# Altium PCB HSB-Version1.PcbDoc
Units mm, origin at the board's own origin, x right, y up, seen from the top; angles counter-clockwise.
Board outline 50.75 x 45.25 mm, 2 copper layers (Top Layer, Bottom Layer); 31 components, 31 nets, 155 pads, 0 vias.
Unrouted connection lines stored in the file: 86.
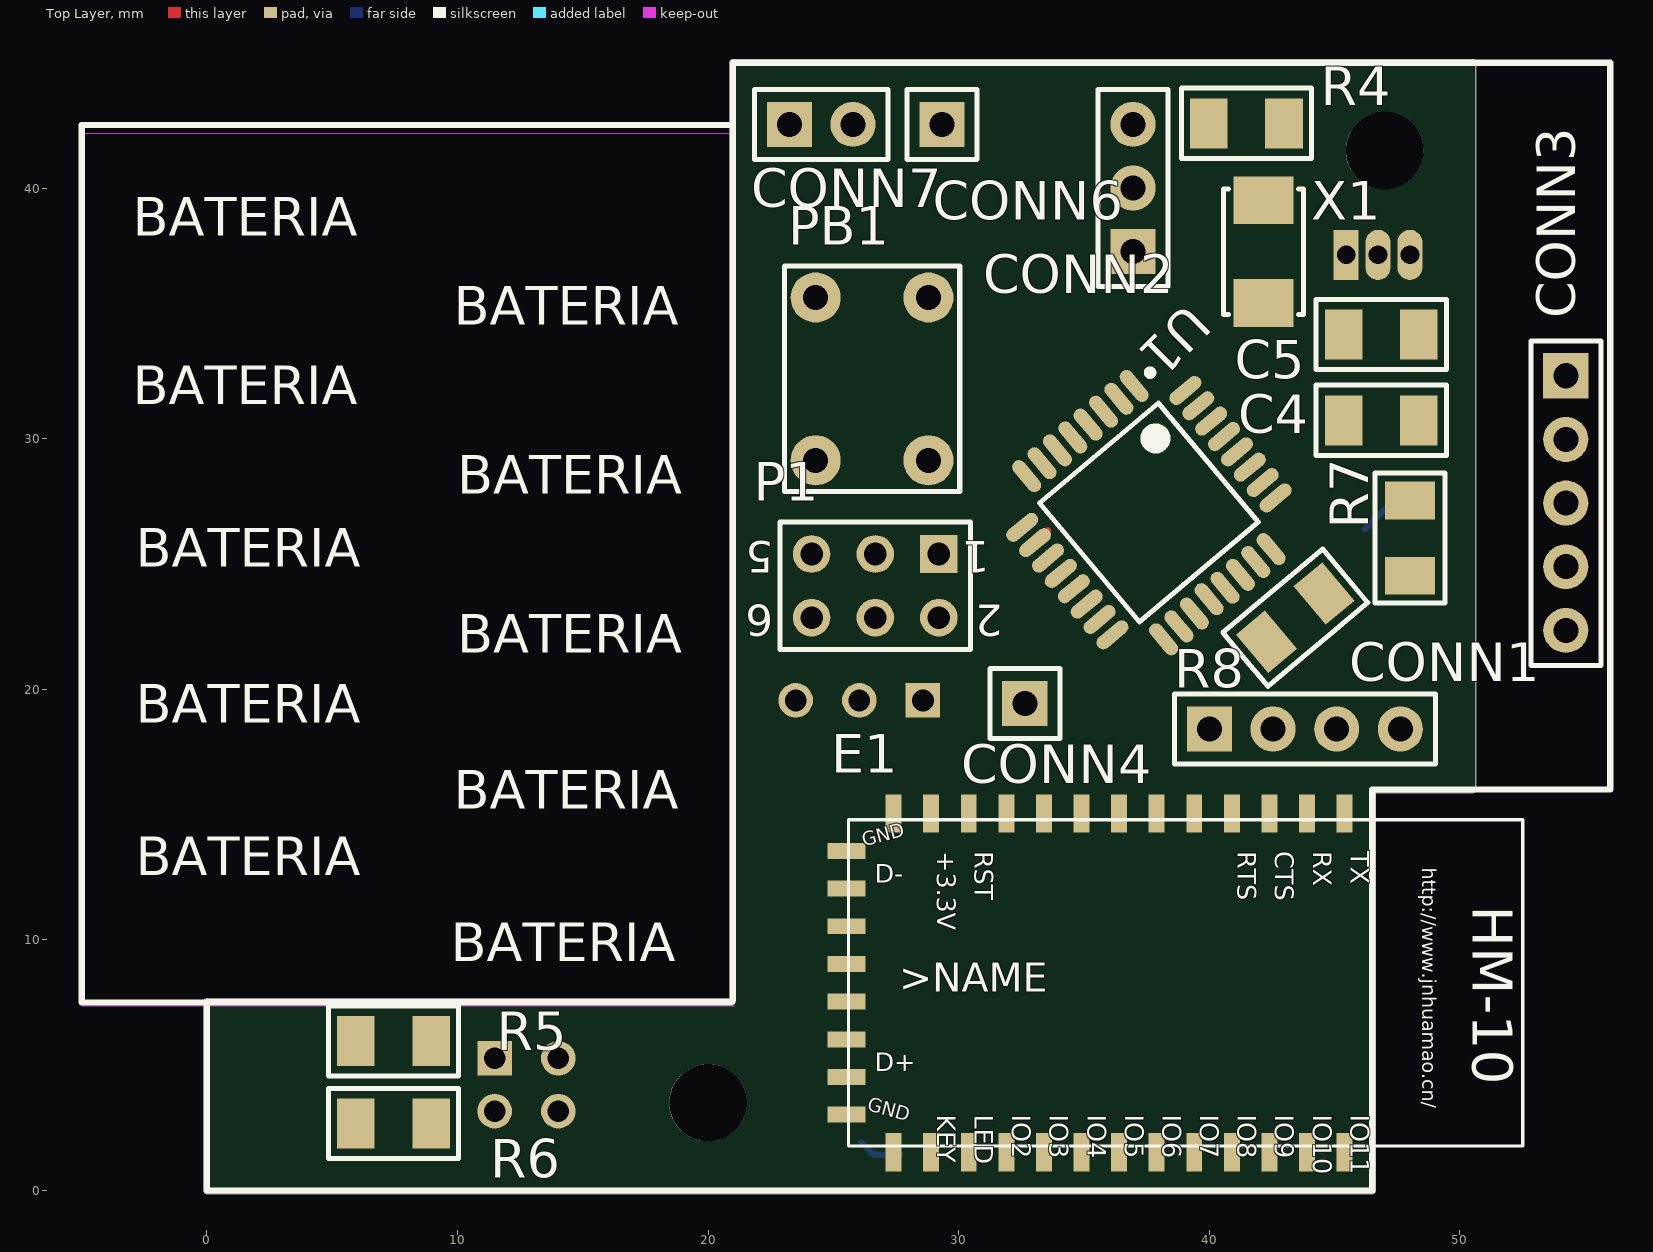
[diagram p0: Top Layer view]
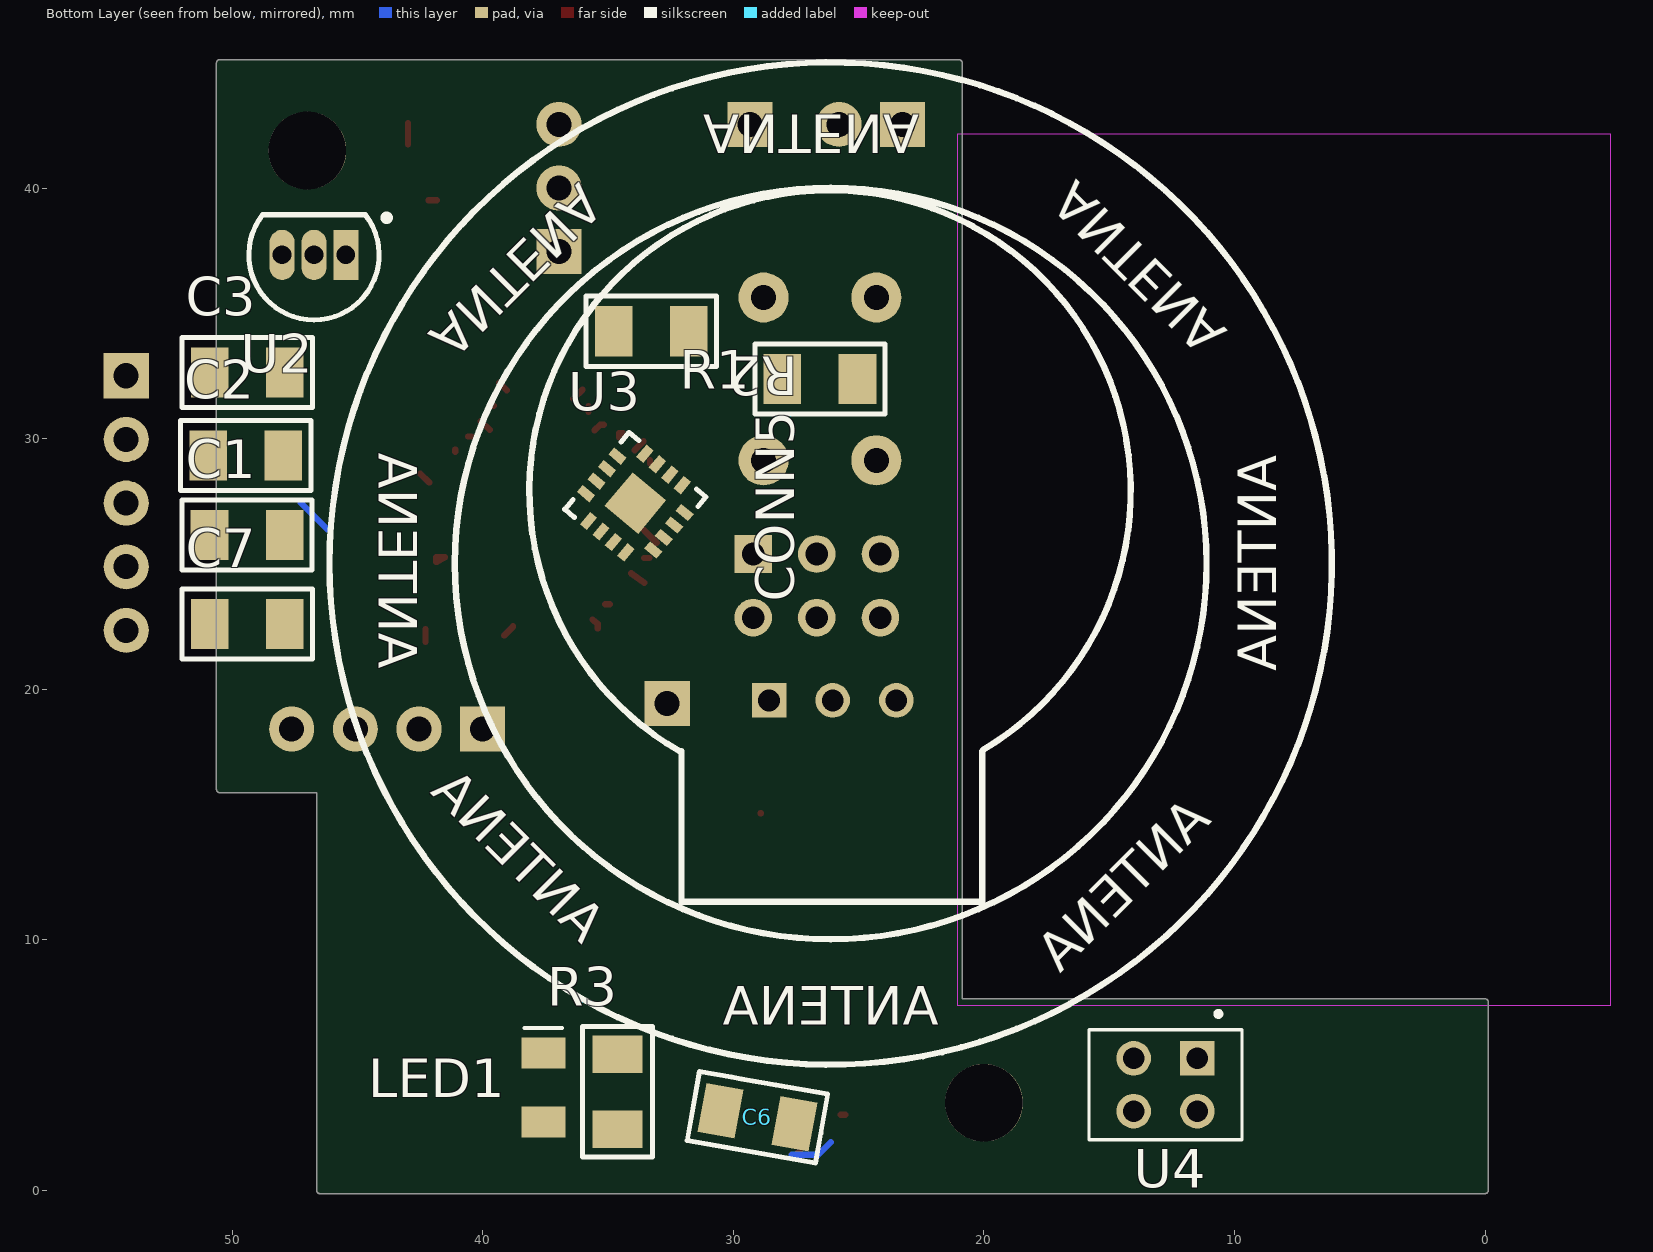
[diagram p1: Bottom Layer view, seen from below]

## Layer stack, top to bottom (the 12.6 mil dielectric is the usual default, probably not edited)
Top Solder: solder mask 0.0102, Solder Resist, Dk 3.5
Top Layer: signal copper 0.0356
Dielectric1: dielectric 0.32, FR-4, Dk 4.8
Bottom Layer: signal copper 0.0356
Bottom Solder: solder mask 0.0102, Solder Resist, Dk 3.5

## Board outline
-0.127,0 -0.127,7.519 cw(c0,7.519) 0,7.646 20.868,7.646 20.868,45 cw(c20.995,45) 20.995,45.127 50.499,45.127 cw(c50.499,45) 50.5,45.127 cw(c50.5,45) 50.627,45 50.627,16.002 cw(c50.5,16.002) 50.5,15.875 46.627,15.875 46.627,0 cw(c46.5,0) 46.5,-0.127 0,-0.127 cw(c0,0)

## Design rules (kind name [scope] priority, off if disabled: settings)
Clearance [All] p1: gap=0.254
PolygonConnect [All] p1: connectstyle=Relief reliefconductorwidth=0.254 reliefentries=4 polygonreliefangle="90 Angle" airgapwidth=0.254
RoomDefinition Temperatura [InComponentClass('Temperatura')] p1: confinementstyle=ConfineIn formatcopy=TRUE lockcomponents=FALSE outline 38.562,44.492 38.562,28.744 54.945,28.744 54.945,44.492
RoutingVias [All] p1: holewidth=0.711 width=1.27 viastyle="Through Hole" minholewidth=0.711 minwidth=1.27 maxholewidth=0.711 maxwidth=1.27
SolderMaskExpansion [All] p1: expansion=0.102
Width [All] p1: maxlimit=0.254 minlimit=0.254 preferedwidth=0.254
30 further rules are at their usual default settings.

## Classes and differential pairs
component class PPM: CONN5
component class SensorCaida: C1 C2 C3 CONN3 CONN4 U3
component class Atmega328P: C4 C5 C7 CONN2 CONN6 P1 PB1 R1 R2 R7 R8 U1 X1
component class Temperatura: R4
component class BLE-HM10: C6 CONN1 E1 LED1 R3
component class Proximidad: R5 R6 U4
component class CargaInalambrica: CONN7

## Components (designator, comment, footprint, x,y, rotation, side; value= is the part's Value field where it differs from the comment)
C1 "C" C1206-1.00 49.406,26.162 r0 bottom
C2 "C" C1206-1.00 49.463,29.334 r0 bottom
C3 "C" C1206-1.00 49.403,32.639 r0 bottom
C4 "C1" C1206-1.25 46.863,30.734 r180 top
C5 "C2" C1206-1.25 46.863,34.163 r180 top
C6 "C2" C1206-1.25 29.036,2.921 r10 bottom
C7 "C2" C1206-1.25 49.403,22.606 r180 bottom
CONN1 "Connector" "1x4x2.54 Pin Header TH V" 43.815,18.415 r0 top
CONN2 "Connector" "1x3x2.54 Pin Header TH V" 36.957,40.005 r90 top
CONN3 "Connector" "1x5x2.54 Pin Header TH V" 54.229,27.432 r270 top
CONN4 "Connector" "1x1x2.54 Pin Header TH V" 32.639,19.431 r90 top
CONN5 "Connector" SEN0203 18.796,14.224 r90 bottom
CONN6 "Connector" "1x1x2.54 Pin Header TH V" 29.337,42.545 r90 top
CONN7 "Connector" "1x2x2.54 Pin Header TH V" 24.511,42.545 r0 top
E1 "HM Bluetooth module use TI CC2540 or CC2541, Master and slave roles in one, transmission version and remote control version and PIO state acquisition functions in one, Support the AT command modify module parameters, Convenient and flexible." 26.9X13X2.2_BOARD 45.402,7.544 r270 top
LED1 "LED" SMT1206-LED 37.581,4.108 r90 bottom
P1 "Header 3X2" HDR2X3 29.21,25.4 r180 top
PB1 "Push Button" "Tack Switch 6x6 1mm TH" 26.543,32.385 r270 top
R1 "R" R1206-0.55 26.543,32.385 r0 bottom
R2 "R" R1206-0.55 33.274,34.29 r180 bottom
R3 "R" R1206-0.55 34.624,3.937 r270 bottom
R4 "R" R1206-0.55 41.483,42.587 r180 top
R5 "R" R1206-0.55 7.446,5.969 r180 top
R6 "R" R1206-0.55 7.446,2.667 r180 top
R7 "R" R1206-0.55 48.006,26.035 r270 top
R8 "R" R1206-0.55 43.434,22.86 r40 top
U1 "ATMEGA328P-AU" TQFP80P900X900X120-32N 37.592,27.051 r310 top
U2 "LM35CAZ/NOPB" Z03A 46.736,37.338 r90 bottom
U3 "ADXL335" *LFCSP-16 33.909,27.432 r40 bottom
U4 "QRD1114" *ONS_QRD1114 12.653,4.318 r270 bottom
X1 "XTAL" 2-SMD 42.164,37.465 r270 top

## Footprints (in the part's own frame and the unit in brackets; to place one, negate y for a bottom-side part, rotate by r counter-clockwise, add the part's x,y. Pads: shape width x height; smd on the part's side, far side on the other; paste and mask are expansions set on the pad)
"1x1x2.54 Pin Header TH V" [mm] "1x1x2.54 Pin Header TH V"
  rect 1.8x1.8 hole 1: 1(0,0)
  silkscreen extent -1.4,-1.4 1.4,1.4, body extent -1.27,-1.27 1.27,1.27, height 8.55
"1x2x2.54 Pin Header TH V" [mm] "1x2x2.54 Pin Header TH V"
  rect 1.8x1.8 hole 1: 1(-1.27,0)
  round 1.8 hole 1: 2(1.27,0)
  silkscreen extent -2.67,-1.4 2.67,1.4, body extent -2.54,-1.27 2.54,1.27, height 8.55
"1x3x2.54 Pin Header TH V" [mm] "1x3x2.54 Pin Header TH V"
  rect 1.8x1.8 hole 1: 1(-2.54,0)
  round 1.8 hole 1: 2(0,0) 3(2.54,0)
  silkscreen extent -3.94,-1.4 3.94,1.4, body extent -3.81,-1.27 3.81,1.27, height 8.55
"1x4x2.54 Pin Header TH V" [mm] "1x4x2.54 Pin Header TH V"
  rect 1.8x1.8 hole 1: 1(-3.81,0)
  round 1.8 hole 1: 2(-1.27,0) 3(1.27,0) 4(3.81,0)
  silkscreen extent -5.21,-1.4 5.21,1.4, body extent -5.08,-1.27 5.08,1.27, height 8.55
"1x5x2.54 Pin Header TH V" [mm] "1x5x2.54 Pin Header TH V"
  rect 1.8x1.8 hole 1: 1(-5.08,0)
  round 1.8 hole 1: 2(-2.54,0) 3(0,0) 4(2.54,0) 5(5.08,0)
  silkscreen extent -6.48,-1.4 6.48,1.4, body extent -6.35,-1.27 6.35,1.27, height 8.55
2-SMD [mm] "2-SMD"
  rect 1.9x2.4 smd: 1(-2.05,0) 2(2.05,0)
  silkscreen extent -2.5,-1.6 2.5,1.6, body extent -2.51,-1.6 2.51,1.6, height 1.05
26.9X13X2.2_BOARD [mil]
  rect 60x25 smd: 1(-295.28,0) 2(-295.28,-59.05) 3(-295.28,-118.11) 4(-295.28,-177.16) 5(-295.28,-236.22) 6(-295.28,-295.27) 8(-295.28,-413.39) 9(-295.28,-472.44) 10(-295.28,-531.5) 11(-295.28,-590.55) 12(-295.28,-649.61) 13(-295.28,-708.66) 22(237,-708.66) 23(237,-649.61) 24(237,-590.55) 25(237,-531.5) 26(237,-472.44) 27(237,-413.39) 28(237,-354.33) 29(237,-295.27) 30(237,-236.22) 31(237,-177.16) 32(237,-118.11) 33(237,-59.05) 34(237,0) $7(-295.28,-354.33)
  rect 25x60 smd: 14(-236.22,-782.48) 15(-177.17,-782.48) 16(-118.11,-782.48) 17(-59.06,-782.48) 18(0,-782.48) 19(60,-782.48) 20(119,-782.48) 21(178,-782.48)
  silkscreen extent -285,-780 227,280, body extent -286,-785 226,274, height 61
*LFCSP-16 [mm]
  rect 1.75x1.75 smd: 0(0,0)
  rect 0.65x0.37 smd: 1(-1.75,0.975) 2(-1.75,0.325) 3(-1.75,-0.325) 4(-1.75,-0.975) 9(1.75,-0.975) 10(1.75,-0.325) 11(1.75,0.325) 12(1.75,0.975)
  rect 0.37x0.65 smd: 5(-0.975,-1.75) 6(-0.325,-1.75) 7(0.325,-1.75) 8(0.975,-1.75) 13(0.975,1.75) 14(0.325,1.75) 15(-0.325,1.75) 16(-0.975,1.75)
  silkscreen extent -2,-2 2,2
*ONS_QRD1114 [mm]
  rect 1.378x1.378 hole 0.87: 1(-0.955,1.17)
  round 1.378 hole 0.87: 2(-0.955,-1.37) 3(1.155,-1.37) 4(1.155,1.17)
  silkscreen extent -2.83,-3.15 2.29,2.95
C1206-1.00 [mm] "Capacitor Chip 1206 Height 1.00mm"
  rect 1.5x2 smd: 1(-1.5,0) 2(1.5,0)
  silkscreen extent -2.6,-1.4 2.6,1.4, body extent -1.6,-0.81 1.6,0.81, height 1.01
C1206-1.25 [mm] "Capacitor Chip 1206 Height 1.25mm"
  rect 1.5x2 smd: 1(-1.5,0) 2(1.5,0)
  silkscreen extent -2.6,-1.4 2.6,1.4, body extent -1.6,-0.81 1.6,0.81, height 1.26
HDR2X3 [mm] "Connector; Header; 3x2 Position"
  rect 1.5x1.5 hole 0.9: 1(0,0)
  round 1.5 hole 0.9: 2(0,2.54) 3(2.54,0) 4(2.54,2.54) 5(5.08,0) 6(5.08,2.54)
  silkscreen extent -1.27,-1.27 6.35,3.81
R1206-0.55 [mm] "Resistor Chip 1206 Height 0.55mm"
  rect 1.5x2 smd: 1(-1.5,0) 2(1.5,0)
  silkscreen extent -2.6,-1.4 2.6,1.4, body extent -1.6,-0.8 1.6,0.8, height 0.56
SEN0203 [mil] "Sensor PPM"
  rect 54.25x54.25 hole 34.25: 1(210,385)
  round 54.25 hole 34.25: 2(210,285) 3(210,185)
  silkscreen extent -106,-183 1012,762
SMT1206-LED [mm]
  rect 1.25x1.75 smd: 1(-1.375,0) 2(1.375,0)
  silkscreen extent 2.37,-0.75 2.37,0.75, body extent -1.6,-0.8 1.6,0.8, height 1.78
"Tack Switch 6x6 1mm TH" [mm] "Tack Switch 6x6mm, 1mm button height TH"
  round 2 hole 1: 1(-3.25,2.25) 1(3.25,2.25) 2(-3.25,-2.25) 2(3.25,-2.25)
  silkscreen extent -4.5,-3.5 4.5,3.5, body extent -3.98,-3 3.98,3, height 4.41
TQFP80P900X900X120-32N [mm] "TQFP, 32-Leads, Body 7.00x7.00mm, Pitch 0.80mm, IPC Medium Density"
  oval 1.5x0.55 smd: 1(-4.25,2.8) 2(-4.25,2) 3(-4.25,1.2) 4(-4.25,0.4) 5(-4.25,-0.4) 6(-4.25,-1.2) 7(-4.25,-2) 8(-4.25,-2.8) 17(4.25,-2.8) 18(4.25,-2) 19(4.25,-1.2) 20(4.191,-0.381) 21(4.25,0.4) 22(4.25,1.2) 23(4.25,2) 24(4.25,2.8)
  oval 0.55x1.5 smd: 9(-2.8,-4.25) 10(-2,-4.25) 11(-1.2,-4.25) 12(-0.4,-4.25) 13(0.4,-4.25) 14(1.2,-4.25) 15(2,-4.25) 16(2.8,-4.25) 25(2.8,4.25) 26(2,4.25) 27(1.2,4.25) 28(0.4,4.25) 29(-0.4,4.25) 30(-1.2,4.25) 31(-2,4.25) 32(-2.8,4.25)
  silkscreen extent -4.37,-3.1 3.1,3.75, body extent -4.45,-4.5 4.55,4.5, height 1.6
Z03A [mm] "TO, Flat Index; 3 In-Line, Axial Leads; Body Dia. 5mm; Leads 0.55 x 0.50 mm (max)"
  rect 2x1 hole 0.75: 1(0,-1.27)
  oval 2x1 hole 0.75: 2(0,0) 3(0,1.27)
  silkscreen extent -2.6,-3.02 1.6,2.6, body extent -2.61,-2.61 1.6,2.61, height 5.2

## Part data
C1 C2 C3: "Capacitor, generic"
C4 C5 C6 C7: library part C, "Capacitor, generic"
CONN1: library part "Header 1x4"
CONN2 CONN5: library part "Header 1x3"
CONN3: library part "Header 1x5"
CONN4 CONN6: library part "Header 1x1"
CONN7: library part "Header 1x2"
E1: library part HM-10-BOARD
LED1: "*"
P1: "Header, 3-Pin, Dual row"
R1 R2 R3 R4 R5 R6 R7 R8: "Resistor, generic"
U1: "Microchip Technology ATMEGA328P-AN, 8bit AVR Microcontroller, 20MHz, 32 kB Flash, 32-Pin TQFP"
U2: "Precision Centigrade Temperature Sensor, 3-pin TO-92, Pb-Free"
U3: "Acelerómetro X, Y, Eje Z ± 3g 1.6kHz _X, Y_, 550Hz _Z_ 16-LFCSP-LQ _4x4_"
U4: "Sensor óptico reflectante 0.050 _1.27 mm_ radial - 4 conductores"
X1: "Crystal, Generic"

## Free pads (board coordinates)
  round 3.1 hole 3.1: 0(20,3.5) 1(47,41.5)

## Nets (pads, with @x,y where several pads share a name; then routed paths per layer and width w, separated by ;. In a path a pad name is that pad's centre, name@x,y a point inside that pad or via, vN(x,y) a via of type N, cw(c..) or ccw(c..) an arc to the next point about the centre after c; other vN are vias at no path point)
3.3V: CONN7.1 P1.2 R1.1 R7.2 U1.4 U1.6 U1.18 | length 1.5
  Top Layer w0.254: U1.6@33.583,29.899 U1.6 ; U1.4 35.31,30.564 U1.4@35.538,30.335 ; U1.18 38.792,22.502 U1.18@39.145,22.149
A0: CONN5.1 U1.23 | length 0.9
  Top Layer w0.254: U1.23@41.507,25.273 41.856,25.273 U1.23 U1.23@41.507,25.273
A1: C6.2 CONN1.4 E1.12 U1.24 | length 0
  Top Layer w0.254: E1.12 E1.12@28.902,15.062
A2: C1.1 CONN3.2 U1.25 U3.12 | length 1.5
  Bottom Layer w0.254: 46.206,26.391 46.942,27.126 47.261,27.445
A3: CONN3.3 U1.26 U3.10 | length 0.5
  Top Layer w0.254: U1.26 U1.26@42.497,28.6
A4: C3.1 CONN3.4 U1.27 U3.8
A5: R7.1 R8.2 U1.28 | length 0.1
  Top Layer w0.254: U1.28 U1.28@41.105,29.569
AREF: C7.2 U1.20
C_BAT: CONN6.1 U1.32 | length 0.4
  Top Layer w0.254: U1.32 U1.32@39.348,32.233
D0: CONN2.2 U1.30 | length 0.5
  Top Layer w0.254: U1.30@39.727,30.353 U1.30
D1: CONN2.1 U1.31 | length 0.2
  Top Layer w0.254: U1.31 U1.31@39.726,31.315
D3: CONN1.2 E1.2 U1.1
D4: CONN1.3 E1.1 U1.2 | length 0.5
  Top Layer w0.254: U1.2@36.021,31.953 U1.2
D5: R4.2 U1.9 U2.1 | length 0.8
  Top Layer w0.254: U2.1 U2.1@45.466,38.153
D6: R4.1 U1.10 U2.2 | length 1.5
  Top Layer w0.254: U1.10 33.069,25.851 U1.10@33.557,26.34 ; R4.1@42.983,41.751 R4.1
D7: CONN5.2 U1.11 | length 0.2
  Top Layer w0.254: U1.11@33.345,25.238 U1.11
D8: R5.2 R6.2 U1.12 | length 0.6
  Top Layer w0.254: U1.12@33.557,24.257 U1.12
D9: R5.1 U1.13 U4.1
D10: CONN3.1 U1.14 U3.14 U3.15 | length 0.2
  Top Layer w0.254: U1.14@34.929,23.4 U1.14
D11: P1.4 U1.15 | length 1.1
  Top Layer w0.254: P1.4 P1.4@27.309,22.86 ; U1.15@35.411,22.428 35.411,22.611 U1.15
D12: P1.1 U1.16
D13: P1.3 U1.17
GND: C2.2 C3.2 C4.1 C5.1 C6.1 C7.1 CONN1.1 CONN2.3 CONN3.5 CONN5.3 CONN7.2 E1.13 E1.14 E1.21 E1.22 LED1.2 P1.6 PB1.2 R8.1 U1.3 U1.5 U1.21 U2.3 U3.3 U3.5 U3.6 U3.7 U4.2 U4.4 | length 3.4
  Top Layer w0.254: E1.21 E1.21@25.709,3.023 ; E1.22@27.339,1.524 E1.22 E1.22@27.402,1.397 ; U1.3 U1.3@35.779,31.293 ; R8.1 R8.1@42.285,22.398 ; U1.5@34.406,30.226 34.554,30.226 U1.5 U1.5@34.406,30.226
  Bottom Layer w0.254: 26.115,1.922 26.615,1.422 26.617,1.42 27.559,1.42 27.662,1.42
NET-X1: C4.2 U1.7 X1.2 | length 0.1
  Top Layer w0.254: U1.7 U1.7@33.328,29.134
NET-X2: C5.2 U1.8 X1.1 | length 0.3
  Top Layer w0.254: X1.1@41.838,39.515 X1.1
PINRESET: R2.1 U1.29 | length 0.1
  Top Layer w0.254: U1.29@40.456,30.089 U1.29
RES1K: R6.1 U4.3
RST_PROG: E1.23 P1.5 PB1.1 R1.2 R2.2
ST: CONN4.1 U3.2
VLED: LED1.1 R3.2
VRES: E1.24 R3.1
pads on no net: C1.2 C2.1 E1.3 E1.4 E1.5 E1.6 E1.8 E1.9 E1.10 E1.11 E1.15 E1.16 E1.17 E1.18 E1.19 E1.20 E1.25 E1.26 E1.27 E1.28 E1.29 E1.30 E1.31 E1.32 E1.33 E1.34 E1.$7 U1.19 U1.22 U3.0 U3.1 U3.4 U3.9 U3.11 U3.13 U3.16

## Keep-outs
Keep-Out Layer:
  rectangle: -5,7.366 21.035,42.164

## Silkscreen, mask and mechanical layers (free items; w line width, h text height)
Top Overlay:
  lines w0.254: -5,7.5 20.934,7.5 ; -5,7.519 -5,42.519 20.995,42.519 ; 46.5,16.002 46.5,0 0,0 0,2.185 0,7.519 20.934,7.519 20.995,7.58 20.995,45 56.007,45 56.007,16.002 46.562,16.002
  text "BATERIA" at -2.968,38.1 h1.52
  text "BATERIA" at 9.859,34.544 h1.52
  text "BATERIA" at -2.968,31.369 h1.52
  text "BATERIA" at 9.986,27.813 h1.52
  text "BATERIA" at -2.841,24.892 h1.52
  text "BATERIA" at 9.986,21.463 h1.52
  text "BATERIA" at -2.841,18.669 h1.52
  text "BATERIA" at 9.859,15.24 h1.52
  text "BATERIA" at -2.841,12.573 h1.52
  text "BATERIA" at 9.732,9.144 h1.52
Bottom Overlay:
  circle w0.254: c26.115,25.019 r15
  circle w0.254: c26.115,25.019 r20
  text "ANTENA" at 31.195,42.926 h1.52 r180
  text "ANTENA" at 16.336,40.386 h1.52 r225
  text "ANTENA" at 42.244,34.163 h1.52 r135
  text "ANTENA" at 8.335,29.337 h1.52 r270
  text "ANTENA" at 44.149,20.828 h1.52 r90
  text "ANTENA" at 10.875,14.732 h1.52 r315
  text "ANTENA" at 36.021,9.779 h1.52 r45
  text "ANTENA" at 21.797,6.604 h1.52

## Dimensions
0,2.185 to 56.007,16.002 on Mechanical 15
0,0 to -5,7.5 on Mechanical 15
0,0 to 20.995,45 on Mechanical 15
-4.959,29.734 to 21.036,29.734 on Mechanical 15
-5,42.519 to -5,7.519 on Mechanical 15
47,41.5 to 56.007,45 on Mechanical 15
47,41.5 to 56.007,45 on Mechanical 15
46.5,0 to 56.007,16.002 on Mechanical 15
56.007,16.002 to 56.007,45 on Mechanical 15
20,3.5 to 46.5,0 on Mechanical 15
20,3.5 to 0,0 on Mechanical 15
20,3.5 to 0,2.185 on Mechanical 15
